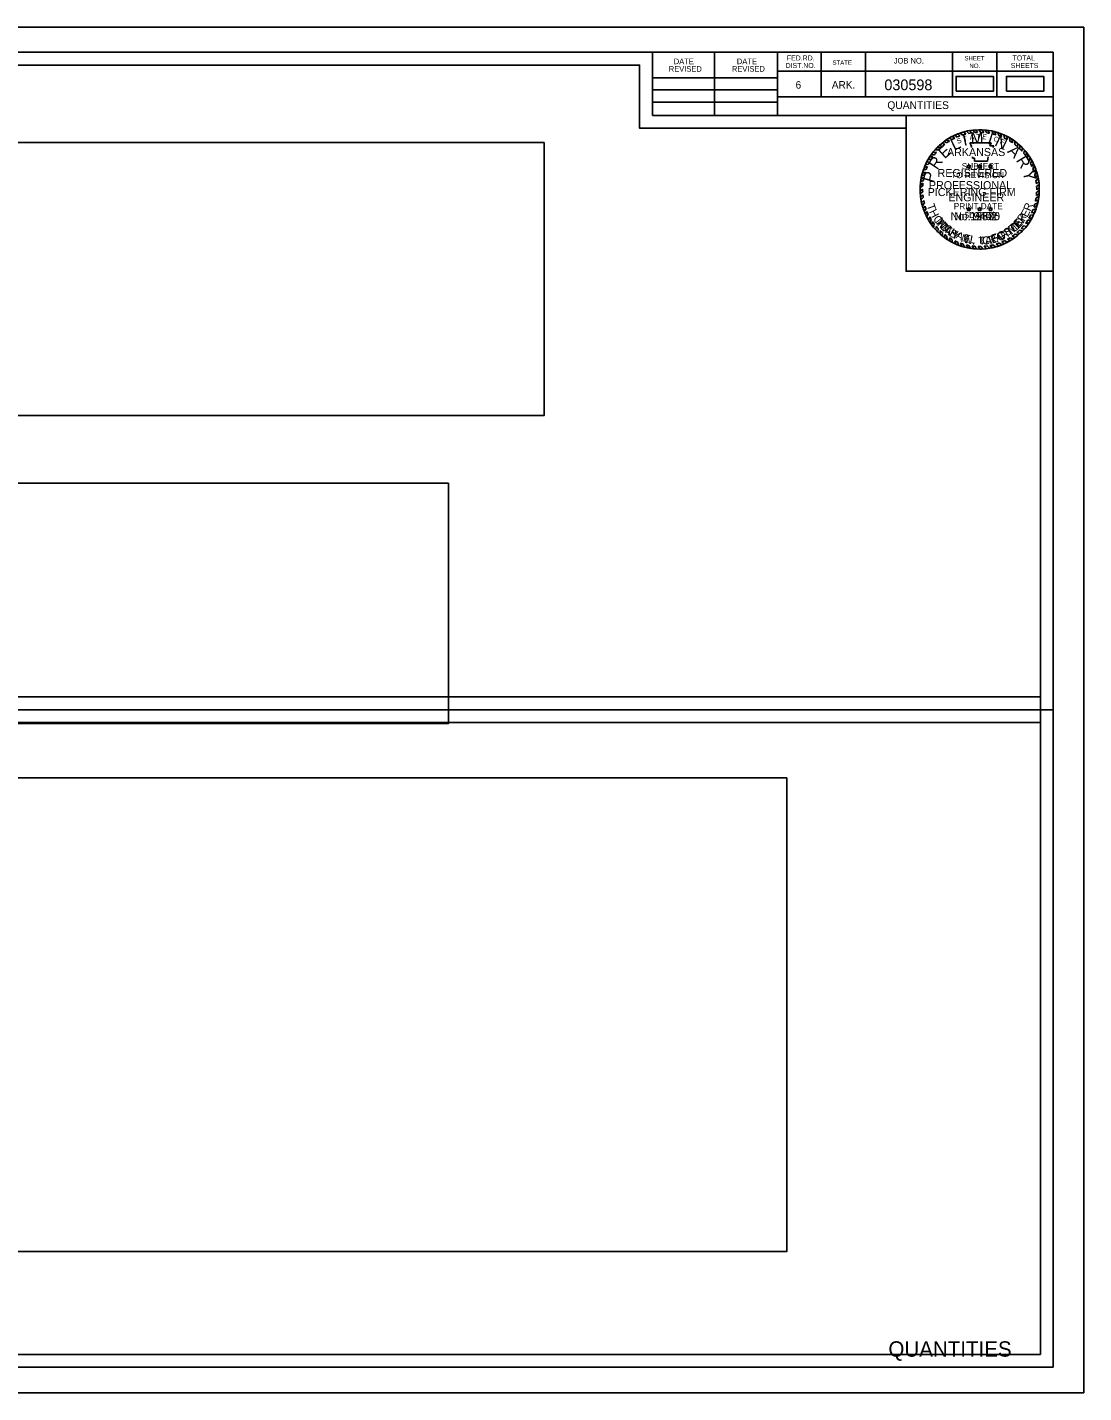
# Model space of a CAD drawing. Extents: x 1369904 to 1372237, y 380119 to 380332.
# Drawn here: x 1371071.9 to 1371236.9, y 380119.1 to 380332.4 of the extents above; entities that cross this region are included whole.
import ezdxf

# ---------------------------------------------------------------- set-up
doc = ezdxf.new("R2010")
doc.units = 0
for name, color, linetype in [('Default', 7, 'Continuous'), ('R_Border', 7, 'Continuous'), ('R_Border Notes', 7, 'Continuous'), ('R_Border Plan-Plan', 7, 'Continuous'), ('R_Border Title', 7, 'Continuous'), ('R_No Plot', 7, 'Continuous'), ('STAMP_PE_CRAFTON', 7, 'Continuous'), ('STAMP_PE_FOSTER', 7, 'Continuous'), ('STAMP_PE_SEAL-INFO', 7, 'Continuous'), ('STAMP_PE_TAEGTMEYER', 7, 'Continuous'), ('STAMP_PE_TXT', 7, 'Continuous'), ('STAMP_PRELIMINARY', 7, 'Continuous')]:
    doc.layers.add(name, color=color, linetype=linetype)

msp = doc.modelspace()

# ---------------------------------------------------------------- linework, layer by layer
at = {"layer": 'Default'}
for points in [[(1371217, 380322.41), (1371222.83, 380322.41), (1371222.83, 380324.72), (1371217, 380324.72)], [(1371224.87, 380322.41), (1371230.7, 380322.41), (1371230.7, 380324.72), (1371224.87, 380324.72)], [(1370987.93, 380271.73), (1371152.6, 380271.73), (1371152.6, 380314.39), (1370987.93, 380314.39)], [(1371002.88, 380223.6), (1371137.65, 380223.6), (1371137.65, 380261.16), (1371002.88, 380261.16)], [(1370963.52, 380141.11), (1371190.53, 380141.11), (1371190.53, 380215.12), (1370963.52, 380215.12)]]:
    msp.add_lwpolyline(points, close=True, dxfattribs=at)
at = {"layer": 'R_Border'}
for p, q in [((1370916, 380328.5), (1371232.18, 380328.5)), ((1371169.54, 380318.62), (1371169.54, 380328.5)), ((1371179.22, 380318.62), (1371179.22, 380328.5)), ((1371189.08, 380328.5), (1371189.08, 380318.62)), ((1371195.92, 380328.5), (1371195.92, 380321.56)), ((1371202.86, 380328.5), (1371202.86, 380321.56)), ((1371216.44, 380328.5), (1371216.44, 380321.56)), ((1371223.38, 380328.5), (1371223.38, 380321.56)), ((1371232.18, 380123.04), (1371232.18, 380328.5)), ((1371232.18, 380325.56), (1371189.08, 380325.56)), ((1371232.18, 380325.58), (1371232.18, 380325.58)), ((1371169.54, 380324.48), (1371189.08, 380324.48)), ((1371169.54, 380322.62), (1371189.08, 380322.62)), ((1371232.18, 380321.56), (1371189.08, 380321.56)), ((1371192.04, 380321.56), (1371232.18, 380321.56)), ((1371169.54, 380320.68), (1371189.08, 380320.68)), ((1371232.18, 380318.62), (1371169.54, 380318.62)), ((1371232.18, 380123.04), (1370916, 380123.04))]:
    msp.add_line(p, q, dxfattribs=at)
at = {"layer": 'R_Border Plan-Plan'}
msp.add_line((1370916, 380225.77), (1371232.18, 380225.77), dxfattribs=at)
at = {"layer": 'R_No Plot'}
for points in [[(1370903.6, 380332.4), (1371236.94, 380332.4), (1371236.94, 380119.06), (1370903.6, 380119.06)], [(1371230.18, 380227.77), (1370918, 380227.77), (1370918, 380326.5), (1371167.54, 380326.5), (1371167.54, 380316.62), (1371185.08, 380316.62), (1371209.18, 380316.62), (1371209.18, 380294.29), (1371230.18, 380294.29)], [(1370918, 380326.5), (1371167.54, 380326.5), (1371167.54, 380316.62), (1371185.08, 380316.62), (1371209.18, 380316.62), (1371209.18, 380294.29), (1371230.18, 380294.29), (1371230.18, 380125.04), (1370918, 380125.04)], [(1371209.18, 380318.62), (1371232.18, 380318.62), (1371232.18, 380294.29), (1371209.18, 380294.29)], [(1370918, 380223.77), (1371230.18, 380223.77), (1371230.18, 380125.04), (1370918, 380125.04)]]:
    msp.add_lwpolyline(points, close=True, dxfattribs=at)
at = {"layer": 'STAMP_PE_SEAL-INFO'}
for p, q in [((1371215.52, 380314.83), (1371215.96, 380314.63)), ((1371215.91, 380315.07), (1371216.34, 380314.85)), ((1371216.36, 380315.33), (1371216.82, 380315.1)), ((1371216.79, 380315.54), (1371217.18, 380315.26)), ((1371217.29, 380315.75), (1371217.59, 380315.43)), ((1371217.64, 380315.88), (1371218.02, 380315.57)), ((1371218.23, 380316.06), (1371218.52, 380315.71)), ((1371218.62, 380316.16), (1371218.98, 380315.82)), ((1371219.1, 380316.26), (1371219.4, 380315.89)), ((1371219.62, 380316.33), (1371219.9, 380315.95)), ((1371220.35, 380315.97), (1371220.04, 380316.37)), ((1371220.85, 380315.98), (1371220.57, 380316.39)), ((1371221.31, 380315.96), (1371221.05, 380316.38)), ((1371221.82, 380315.91), (1371221.52, 380316.35)), ((1371222.24, 380315.84), (1371221.98, 380316.3)), ((1371222.8, 380315.72), (1371222.63, 380316.18)), ((1371223.21, 380315.62), (1371223.05, 380316.09)), ((1371223.66, 380315.47), (1371223.52, 380315.95)), ((1371224.08, 380315.31), (1371223.93, 380315.81)), ((1371224.54, 380315.1), (1371224.43, 380315.6)), ((1371224.98, 380314.87), (1371224.9, 380315.38)), ((1371225.37, 380314.65), (1371225.33, 380315.15)), ((1371225.81, 380314.36), (1371225.77, 380314.88)), ((1371213.38, 380312.86), (1371213.93, 380312.88)), ((1371213.72, 380313.27), (1371214.24, 380313.23)), ((1371214.04, 380313.61), (1371214.59, 380313.57)), ((1371214.38, 380313.94), (1371214.84, 380313.8)), ((1371214.72, 380314.24), (1371215.25, 380314.14)), ((1371215.1, 380314.56), (1371215.56, 380314.36)), ((1371219.16, 380314.36), (1371222.5, 380314.36)), ((1371219.28, 380314.05), (1371219.16, 380314.36)), ((1371219.38, 380313.75), (1371219.28, 380314.05)), ((1371219.39, 380313.64), (1371219.38, 380313.75)), ((1371222.5, 380314.36), (1371222.28, 380313.87)), ((1371222.28, 380313.87), (1371222.91, 380313.87)), ((1371222.91, 380313.87), (1371222.76, 380313.64)), ((1371226.17, 380314.1), (1371226.2, 380314.58)), ((1371226.61, 380313.72), (1371226.63, 380314.25)), ((1371226.92, 380313.43), (1371226.99, 380313.93)), ((1371227.28, 380313.06), (1371227.35, 380313.58)), ((1371227.56, 380312.74), (1371227.69, 380313.21)), ((1371227.88, 380312.32), (1371228.02, 380312.82)), ((1371212.01, 380310.5), (1371212.52, 380310.64)), ((1371212.2, 380310.93), (1371212.7, 380311.03)), ((1371212.39, 380311.32), (1371212.88, 380311.38)), ((1371212.62, 380311.74), (1371213.11, 380311.76)), ((1371212.86, 380312.14), (1371213.38, 380312.18)), ((1371213.1, 380312.49), (1371213.6, 380312.48)), ((1371219.58, 380311.93), (1371219.55, 380312.15)), ((1371219.89, 380311.93), (1371219.58, 380311.93)), ((1371219.89, 380311.5), (1371219.89, 380311.93)), ((1371221.92, 380311.5), (1371219.89, 380311.5)), ((1371221.94, 380311.84), (1371221.92, 380311.5)), ((1371222.02, 380312.15), (1371221.94, 380311.84)), ((1371228.1, 380312.01), (1371228.28, 380312.47)), ((1371228.41, 380311.51), (1371228.59, 380312)), ((1371228.61, 380311.14), (1371228.84, 380311.59)), ((1371228.84, 380310.66), (1371229.07, 380311.15)), ((1371228.98, 380310.32), (1371229.24, 380310.76)), ((1371211.88, 380308.48), (1371211.44, 380308.25)), ((1371211.97, 380308.94), (1371211.5, 380308.69)), ((1371211.6, 380309.18), (1371212.07, 380309.37)), ((1371211.71, 380309.59), (1371212.19, 380309.76)), ((1371211.86, 380310.09), (1371212.35, 380310.23)), ((1371229.18, 380309.77), (1371229.45, 380310.25)), ((1371229.28, 380309.41), (1371229.58, 380309.86)), ((1371229.42, 380308.85), (1371229.73, 380309.3)), ((1371229.49, 380308.47), (1371229.84, 380308.82)), ((1371211.79, 380307.62), (1371211.36, 380307.36)), ((1371211.77, 380307.12), (1371211.36, 380306.79)), ((1371211.78, 380306.72), (1371211.38, 380306.39)), ((1371211.82, 380308.04), (1371211.39, 380307.76)), ((1371229.55, 380307.96), (1371229.92, 380308.3)), ((1371229.55, 380306.11), (1371229.98, 380306.37)), ((1371229.58, 380307.54), (1371229.97, 380307.84)), ((1371229.59, 380306.62), (1371230, 380306.9)), ((1371229.6, 380307.03), (1371230, 380307.35)), ((1371211.81, 380306.22), (1371211.44, 380305.86)), ((1371211.86, 380305.79), (1371211.51, 380305.42)), ((1371211.94, 380305.33), (1371211.6, 380304.96)), ((1371212.03, 380304.91), (1371211.72, 380304.5)), ((1371212.16, 380304.47), (1371211.86, 380304.05)), ((1371229.15, 380304.28), (1371229.64, 380304.48)), ((1371229.3, 380304.77), (1371229.77, 380304.98)), ((1371229.4, 380305.23), (1371229.86, 380305.42)), ((1371229.49, 380305.73), (1371229.94, 380305.95)), ((1371212.3, 380304.04), (1371212.02, 380303.63)), ((1371212.46, 380303.62), (1371212.2, 380303.19)), ((1371212.64, 380303.23), (1371212.41, 380302.77)), ((1371212.87, 380302.77), (1371212.68, 380302.28)), ((1371213.11, 380302.37), (1371212.92, 380301.9)), ((1371213.31, 380302.06), (1371213.2, 380301.51)), ((1371228.2, 380302.27), (1371228.67, 380302.26)), ((1371228.37, 380302.55), (1371228.87, 380302.61)), ((1371228.64, 380303.05), (1371229.13, 380303.12)), ((1371228.8, 380303.39), (1371229.29, 380303.48)), ((1371229.01, 380303.9), (1371229.5, 380304.03)), ((1371213.59, 380301.67), (1371213.49, 380301.14)), ((1371213.89, 380301.29), (1371213.81, 380300.77)), ((1371214.2, 380300.95), (1371214.13, 380300.43)), ((1371214.52, 380300.63), (1371214.49, 380300.1)), ((1371214.86, 380300.32), (1371214.86, 380299.79)), ((1371215.22, 380300.02), (1371215.24, 380299.5)), ((1371226.23, 380300.09), (1371226.7, 380299.95)), ((1371226.5, 380300.32), (1371226.98, 380300.19)), ((1371226.91, 380300.69), (1371227.35, 380300.55)), ((1371227.16, 380300.95), (1371227.64, 380300.86)), ((1371227.55, 380301.38), (1371228.01, 380301.3)), ((1371227.86, 380301.78), (1371228.36, 380301.78)), ((1371215.56, 380299.77), (1371215.6, 380299.25)), ((1371215.99, 380299.49), (1371216.05, 380298.98)), ((1371216.34, 380299.28), (1371216.43, 380298.77)), ((1371216.82, 380299.03), (1371216.98, 380298.51)), ((1371217.19, 380298.87), (1371217.37, 380298.35)), ((1371217.69, 380298.67), (1371217.89, 380298.17)), ((1371218.09, 380298.54), (1371218.32, 380298.05)), ((1371218.6, 380298.4), (1371218.82, 380297.93)), ((1371219, 380298.31), (1371219.25, 380297.86)), ((1371219.5, 380298.23), (1371219.74, 380297.79)), ((1371219.94, 380298.19), (1371220.21, 380297.76)), ((1371220.42, 380298.16), (1371220.72, 380297.74)), ((1371220.88, 380298.16), (1371221.23, 380297.76)), ((1371221.4, 380298.18), (1371221.73, 380297.8)), ((1371221.84, 380298.23), (1371222.21, 380297.87)), ((1371222.28, 380298.3), (1371222.67, 380297.96)), ((1371222.78, 380298.4), (1371223.15, 380298.08)), ((1371223.24, 380298.53), (1371223.65, 380298.23)), ((1371223.73, 380298.69), (1371224.17, 380298.42)), ((1371224.15, 380298.85), (1371224.57, 380298.59)), ((1371224.61, 380299.06), (1371225.09, 380298.85)), ((1371225.01, 380299.28), (1371225.43, 380299.04)), ((1371225.43, 380299.52), (1371225.88, 380299.33)), ((1371225.77, 380299.75), (1371226.21, 380299.56))]:
    msp.add_line(p, q, dxfattribs=at)
for radius, start, end in [(9.32, 123.6199, 126.5906), (9.32, 117.6544, 120.8099), (8.91, 115.6869, 119.1583), (9.32, 111.3124, 114.7026), (8.91, 110.3086, 113.1659), (9.32, 105.2339, 109.0352), (8.91, 104.0352, 107.3615), (9.32, 99.7525, 102.7765), (8.91, 98.258, 101.0329), (9.32, 93.9381, 96.5517), (8.91, 92.1102, 95.0367), (9.32, 87.7298, 90.6707), (8.91, 85.9628, 88.9097), (9.32, 81.9732, 84.8236), (8.91, 79.9264, 82.696), (9.32, 75.3125, 77.9426), (8.91, 73.5575, 76.2314), (9.32, 69.6061, 72.3058), (8.91, 67.6248, 70.504), (9.32, 63.1329, 66.2704), (8.91, 61.1558, 64.3784), (9.32, 56.9003, 60.0942), (9.32, 141.6056, 144.4486), (8.91, 139.301, 142.5873), (9.32, 135.4021, 138.3031), (8.91, 133.1331, 136.2562), (9.32, 129.7326, 132.5376), (8.91, 127.5297, 130.9683), (8.91, 121.9746, 125.11), (8.91, 54.9238, 58.2702), (8.91, 48.3016, 52.0395), (9.32, 50.3492, 53.7159), (8.91, 42.2212, 45.5512), (9.32, 44.3405, 47.3929), (8.91, 36.135, 39.5311), (9.32, 38.1247, 41.2316), (9.32, 152.864, 155.5189), (8.91, 156.3402, 159.2319), (9.32, 147.0072, 149.899), (8.91, 151.0315, 153.573), (8.91, 145.0197, 148.2104), (8.91, 29.9032, 33.6645), (9.32, 31.9614, 35.4294), (8.91, 23.7732, 27.2211), (9.32, 25.9391, 29.0125), (9.32, 19.9538, 23.3141), (9.32, 170.0003, 172.6878), (9.32, 164.3068, 166.894), (9.32, 158.4077, 161.0701), (8.91, 167.9048, 170.9039), (8.91, 162.4331, 165.0013), (8.91, 17.6802, 21.4251), (8.91, 11.5444, 15.2364), (8.91, 5.7599, 9.0606), (9.32, 13.8421, 17.4447), (9.32, 7.5852, 10.8621), (9.32, 175.7409, 178.2066), (9.32, 181.7251, 184.1626), (8.91, 179.6454, 182.2633), (8.91, 173.73, 176.4734), (8.91, 353.8632, 357.1274), (8.91, 359.7329, 3.0639), (9.32, 1.7215, 4.7268), (9.32, 355.7156, 358.9569), (9.32, 187.4204, 190.1927), (9.32, 193.0369, 195.9973), (8.91, 185.4539, 188.234), (8.91, 191.2274, 193.9858), (8.91, 196.9675, 199.8353), (8.91, 341.777, 345.0925), (8.91, 348.0778, 351.3435), (9.32, 343.8925, 347.035), (9.32, 349.8305, 353.0885), (9.32, 198.8967, 201.6281), (9.32, 204.5479, 207.4328), (8.91, 202.7761, 205.4791), (9.32, 210.8636, 213.6571), (8.91, 208.7883, 211.7934), (8.91, 214.1838, 217.2747), (8.91, 323.5851, 327.4407), (9.32, 325.4405, 328.9872), (8.91, 329.5549, 333.2076), (8.91, 335.6038, 339.1858), (9.32, 331.4037, 334.9332), (9.32, 337.3837, 340.9933), (9.32, 216.6115, 219.491), (9.32, 222.48, 225.3801), (8.91, 220.3909, 223.3056), (9.32, 228.3665, 231.348), (8.91, 226.2494, 229.2407), (8.91, 232.229, 234.9336), (8.91, 304.823, 308.5143), (9.32, 306.3721, 310.208), (8.91, 310.7744, 314.3161), (9.32, 312.4518, 315.6633), (8.91, 316.6531, 320.3711), (9.32, 318.2846, 321.8043), (9.32, 234.295, 236.9452), (8.91, 238.2223, 240.8353), (9.32, 240.1977, 242.8613), (8.91, 244.3204, 246.9486), (9.32, 246.576, 249.1558), (8.91, 250.3491, 253.1216), (9.32, 252.5967, 255.3252), (8.91, 256.505, 259.1192), (9.32, 258.4433, 261.1398), (8.91, 262.3783, 265.2012), (9.32, 264.1978, 267.1009), (8.91, 268.3215, 271.277), (9.32, 270.2548, 273.3361), (8.91, 274.6157, 277.4486), (9.32, 276.4239, 279.4357), (8.91, 280.3459, 283.5814), (9.32, 282.3199, 285.3702), (8.91, 286.6423, 289.9783), (9.32, 288.5709, 291.9733), (8.91, 292.8745, 296.1185), (9.32, 294.6481, 298.2166), (8.91, 299.0768, 302.1724), (9.32, 300.621, 303.8703)]:
    msp.add_arc((1371220.68, 380307.07), radius, start, end, dxfattribs=at)
at = {"layer": 'STAMP_PE_TXT'}
for p, q in [((1371218.86, 380310.64), (1371218.66, 380310.78)), ((1371218.66, 380310.78), (1371218.91, 380310.78)), ((1371218.79, 380310.41), (1371218.86, 380310.64)), ((1371218.98, 380310.55), (1371218.79, 380310.41)), ((1371218.91, 380310.78), (1371218.98, 380311.02)), ((1371218.98, 380311.02), (1371219.06, 380310.78)), ((1371219.18, 380310.41), (1371218.98, 380310.55)), ((1371219.06, 380310.78), (1371219.31, 380310.78)), ((1371219.31, 380310.78), (1371219.11, 380310.64)), ((1371219.11, 380310.64), (1371219.18, 380310.41)), ((1371220.56, 380310.64), (1371220.36, 380310.78)), ((1371220.36, 380310.78), (1371220.61, 380310.78)), ((1371220.48, 380310.41), (1371220.56, 380310.64)), ((1371220.68, 380310.55), (1371220.48, 380310.41)), ((1371220.61, 380310.78), (1371220.68, 380311.02)), ((1371220.68, 380311.02), (1371220.76, 380310.78)), ((1371220.88, 380310.41), (1371220.68, 380310.55)), ((1371220.76, 380310.78), (1371221, 380310.78)), ((1371221, 380310.78), (1371220.81, 380310.64)), ((1371220.81, 380310.64), (1371220.88, 380310.41)), ((1371222.26, 380310.64), (1371222.06, 380310.78)), ((1371222.06, 380310.78), (1371222.31, 380310.78)), ((1371222.18, 380310.41), (1371222.26, 380310.64)), ((1371222.38, 380310.55), (1371222.18, 380310.41)), ((1371222.31, 380310.78), (1371222.38, 380311.02)), ((1371222.38, 380311.02), (1371222.46, 380310.78)), ((1371222.58, 380310.41), (1371222.38, 380310.55)), ((1371222.46, 380310.78), (1371222.7, 380310.78)), ((1371222.7, 380310.78), (1371222.5, 380310.64)), ((1371222.5, 380310.64), (1371222.58, 380310.41)), ((1371218.91, 380304.08), (1371218.98, 380304.31)), ((1371218.98, 380304.31), (1371219.06, 380304.08)), ((1371220.61, 380304.08), (1371220.68, 380304.31)), ((1371220.68, 380304.31), (1371220.76, 380304.08)), ((1371222.31, 380304.08), (1371222.38, 380304.31)), ((1371222.38, 380304.31), (1371222.46, 380304.08)), ((1371218.86, 380303.93), (1371218.66, 380304.08)), ((1371218.66, 380304.08), (1371218.91, 380304.08)), ((1371218.79, 380303.7), (1371218.86, 380303.93)), ((1371218.98, 380303.84), (1371218.79, 380303.7)), ((1371219.18, 380303.7), (1371218.98, 380303.84)), ((1371219.06, 380304.08), (1371219.31, 380304.08)), ((1371219.31, 380304.08), (1371219.11, 380303.93)), ((1371219.11, 380303.93), (1371219.18, 380303.7)), ((1371220.56, 380303.93), (1371220.36, 380304.08)), ((1371220.36, 380304.08), (1371220.61, 380304.08)), ((1371220.48, 380303.7), (1371220.56, 380303.93)), ((1371220.68, 380303.84), (1371220.48, 380303.7)), ((1371220.88, 380303.7), (1371220.68, 380303.84)), ((1371220.76, 380304.08), (1371221, 380304.08)), ((1371221, 380304.08), (1371220.81, 380303.93)), ((1371220.81, 380303.93), (1371220.88, 380303.7)), ((1371222.26, 380303.93), (1371222.06, 380304.08)), ((1371222.06, 380304.08), (1371222.31, 380304.08)), ((1371222.18, 380303.7), (1371222.26, 380303.93)), ((1371222.38, 380303.84), (1371222.18, 380303.7)), ((1371222.58, 380303.7), (1371222.38, 380303.84)), ((1371222.46, 380304.08), (1371222.7, 380304.08)), ((1371222.7, 380304.08), (1371222.5, 380303.93)), ((1371222.5, 380303.93), (1371222.58, 380303.7))]:
    msp.add_line(p, q, dxfattribs=at)
at = {"layer": 'STAMP_PRELIMINARY'}
msp.add_circle((1371220.68, 380307.07), 9.32, dxfattribs=at)

# ---------------------------------------------------------------- texts
at = {"layer": 'R_Border'}
for s, height, p in [('FED.RD.', 0.782, (1371190.56, 380327.22)), ('JOB NO.', 0.879, (1371207.26, 380326.74)), ('SHEET', 0.684, (1371218.3, 380327.22)), ('TOTAL', 0.782, (1371225.82, 380327.22)), ('REVISED', 0.879, (1371172.1, 380325.46)), ('DATE', 0.879, (1371172.88, 380326.64)), ('REVISED', 0.879, (1371181.96, 380325.46)), ('DATE', 0.879, (1371182.74, 380326.64)), ('DIST.NO.', 0.782, (1371190.36, 380326.04)), ('STATE', 0.684, (1371197.68, 380326.54)), ('NO.', 0.684, (1371219.08, 380326.04)), ('SHEETS', 0.782, (1371225.54, 380326.04)), ('6', 1.17, (1371191.92, 380322.82)), ('ARK.', 1.172, (1371197.58, 380322.82))]:
    msp.add_text(s, height=height, dxfattribs=at).set_placement(p)
at = {"layer": 'R_Border Notes'}
for s, height, p in [('030598', 1.68, (1371205.79, 380322.57)), ('QUANTITIES', 1.2, (1371206.25, 380319.64))]:
    msp.add_text(s, height=height, dxfattribs=at).set_placement(p)
at = {"layer": 'R_Border Title'}
msp.add_text('QUANTITIES', height=2.4, dxfattribs=at).set_placement((1371206.42, 380124.69))
at = {"layer": 'STAMP_PE_CRAFTON'}
for s, rotation, p in [('T', 310.7442, (1371213.65, 380301.97)), ('N', 49.2411, (1371226.97, 380301.09)), ('O', 317.6422, (1371214.32, 380301.15)), ('N', 324.4537, (1371215.16, 380300.37)), ('Y', 331.1686, (1371216.19, 380299.65)), ('N', 347.4752, (1371218.25, 380298.74)), ('R', 14.8189, (1371222.25, 380298.52)), ('A', 20.5125, (1371223.36, 380298.82)), ('F', 28.7821, (1371224.34, 380299.2)), ('T', 34.1136, (1371225.26, 380299.71)), ('O', 41.8391, (1371226.12, 380300.31)), ('.', 356.8926, (1371219.48, 380298.46)), ('C', 6.0117, (1371221.15, 380298.41))]:
    msp.add_text(s, height=1.25, rotation=rotation, dxfattribs=at).set_placement(p)
msp.add_text('No. 12370', height=1.25, dxfattribs=at).set_placement((1371216.14, 380302.26))
at = {"layer": 'STAMP_PE_FOSTER'}
for s, rotation, p in [('M', 308.339, (1371213.8, 380302.09)), ('E', 46.9613, (1371226.68, 380301.06)), ('R', 54.5031, (1371227.41, 380301.88)), ('I', 314.1842, (1371214.6, 380301.15)), ('C', 319.8733, (1371214.95, 380300.8)), ('H', 327.7235, (1371215.88, 380300.06)), ('A', 335.7276, (1371216.86, 380299.48)), ('E', 343.5779, (1371218, 380299.01)), ('L', 350.8115, (1371219.06, 380298.73)), ('F', 15.8691, (1371222.72, 380298.82)), ('O', 23.719, (1371223.76, 380299.15)), ('S', 31.7234, (1371224.87, 380299.68)), ('T', 39.4194, (1371225.83, 380300.31)), ('L', 1.2666, (1371220.6, 380298.58)), ('.', 6.8035, (1371221.64, 380298.63))]:
    msp.add_text(s, height=1.2, rotation=rotation, dxfattribs=at).set_placement(p)
msp.add_text('No. 9402', height=1.25, dxfattribs=at).set_placement((1371216.67, 380302.26))
at = {"layer": 'STAMP_PE_TAEGTMEYER'}
for s, rotation, p in [('T', 289.646, (1371212.38, 380304.58)), ('R', 69.57, (1371228.63, 380303.58)), ('H', 296.7339, (1371212.74, 380303.59)), ('O', 303.7708, (1371213.33, 380302.49)), ('M', 314.2033, (1371213.98, 380301.53)), ('E', 46.8094, (1371226.72, 380300.84)), ('Y', 53.9986, (1371227.46, 380301.66)), ('E', 63.0984, (1371228.13, 380302.6)), ('A', 321.0594, (1371214.95, 380300.57)), ('S', 327.8239, (1371215.77, 380299.93)), ('N', 344.2727, (1371217.67, 380298.92)), ('E', 17.6836, (1371222.63, 380298.6)), ('G', 23.3052, (1371223.68, 380298.93)), ('T', 31.466, (1371224.78, 380299.42)), ('M', 39.3, (1371225.68, 380299.97)), ('.', 350.6464, (1371218.88, 380298.59)), ('T', 3.0061, (1371220.55, 380298.39)), ('A', 8.9826, (1371221.59, 380298.44))]:
    msp.add_text(s, height=1.25, rotation=rotation, dxfattribs=at).set_placement(p)
msp.add_text('No. 19605', height=1.25, dxfattribs=at).set_placement((1371216.14, 380302.26))
at = {"layer": 'STAMP_PE_TXT'}
for s, rotation, p in [('S', 23.5541, (1371217.28, 380314.17)), ('T', 16.311, (1371218.2, 380314.54)), ('A', 9.0679, (1371219.17, 380314.8)), ('T', 1.8248, (1371220.15, 380314.93)), ('E', 355.2002, (1371221.06, 380314.93)), ('O', 342.2506, (1371222.79, 380314.66)), ('F', 335.0075, (1371223.76, 380314.32))]:
    msp.add_text(s, height=0.781, rotation=rotation, dxfattribs=at).set_placement(p)
for s, p in [('ARKANSAS', (1371215.58, 380312.28)), ('REGISTERED', (1371214.1, 380309.01)), ('PROFESSIONAL', (1371212.75, 380307.11)), ('ENGINEER', (1371215.79, 380305.21))]:
    msp.add_text(s, height=1.25, dxfattribs=at).set_placement(p)
at = {"layer": 'STAMP_PRELIMINARY'}
for s, rotation, p in [('L', 25.513, (1371216.69, 380313.09)), ('I', 12.5248, (1371218.22, 380313.85)), ('M', 3.1074, (1371219.32, 380314.16)), ('I', 342.3164, (1371221.79, 380314.23)), ('N', 333.9382, (1371222.89, 380313.96)), ('E', 42.3578, (1371215.21, 380311.76)), ('A', 315.6579, (1371224.93, 380312.93)), ('R', 56.2292, (1371214.05, 380310.03)), ('R', 301.3831, (1371226.3, 380311.62)), ('P', 73.913, (1371213.5, 380308.01)), ('Y', 283.2593, (1371227.38, 380309.83))]:
    msp.add_text(s, height=1.8, rotation=rotation, dxfattribs=at).set_placement(p)
for s, height, p in [('SUBJECT', 0.96, (1371217.88, 380310.22)), ('TO REVISION', 0.96, (1371216.22, 380308.83)), ('PICKERING FIRM', 1.25, (1371212.56, 380306.03)), ('PRINT DATE', 0.96, (1371216.64, 380303.98)), ('$DATE$', 0.96, (1371218.32, 380302.6))]:
    msp.add_text(s, height=height, dxfattribs=at).set_placement(p)

doc.saveas('drawing.dxf')
